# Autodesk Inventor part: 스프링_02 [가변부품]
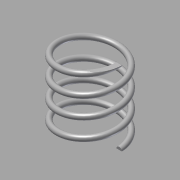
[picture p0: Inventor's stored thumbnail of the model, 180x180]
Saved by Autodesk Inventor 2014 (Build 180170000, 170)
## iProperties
Created: 2015-07
Part Number: 스프링_02 [가변부품]
Material: 강철, 연강
Document SubType Name: Modeling
Designer: Administrator
Mass: 2.74933 g
Surface Area: 9.46891 cm^2
Volume: 0.349788 cm^3
Density: 7.86 g/cm^3
Appearance: 강철
Author: Administrator
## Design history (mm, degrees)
sketch "스케치1"
  geometry: L1 (0, 0)-(-8, 0); L2 (-8, 0)-(-8, 20.5); L3 (-8, 20.5)-(0, 20.5); L4 (0, 20.5)-(0, 0); C1 r 0.75 at (-8, 0)
  constraints: 8 end point, 2 parallel, 1 centre point, 1 coincident, 1 horizontal, 1 perpendicular
  dimensions: "d0" = 16 diameter of L2 L4; "d1" = 20.5 distance of L1.end L2.end (derived); "d2" = 1.5 diameter of C1
feature "코일1" sketch "스케치1" pitch "d3" = 10; turns "d5" = 4; dims "d4" = 20.5 (= d1), "d6" = 0, angle "d7" = 90 deg, angle "d8" = 90 deg, "d9" = 0, "d10" = 0
node "작업 평면1"
sketch "스케치2"
  geometry: L1 (-0.75, 0)-(0.75, 0) reference; 1 further point
  constraints: 1 horizontal alignment
extrude "돌출1" cut sketch "스케치2" distance "d11" = 10; taper "d12" = 0 deg
node "작업 평면2"
sketch "스케치3"
  geometry: L1 (0.75, 0)-(-0.75, 0) reference; 1 further point
  constraints: 1 horizontal alignment
extrude "돌출2" cut sketch "스케치3" distance "d13" = 10; taper "d14" = 0 deg
node "솔리드1"
node "절단 모서리 투영1"
node "절단 모서리 투영2"
